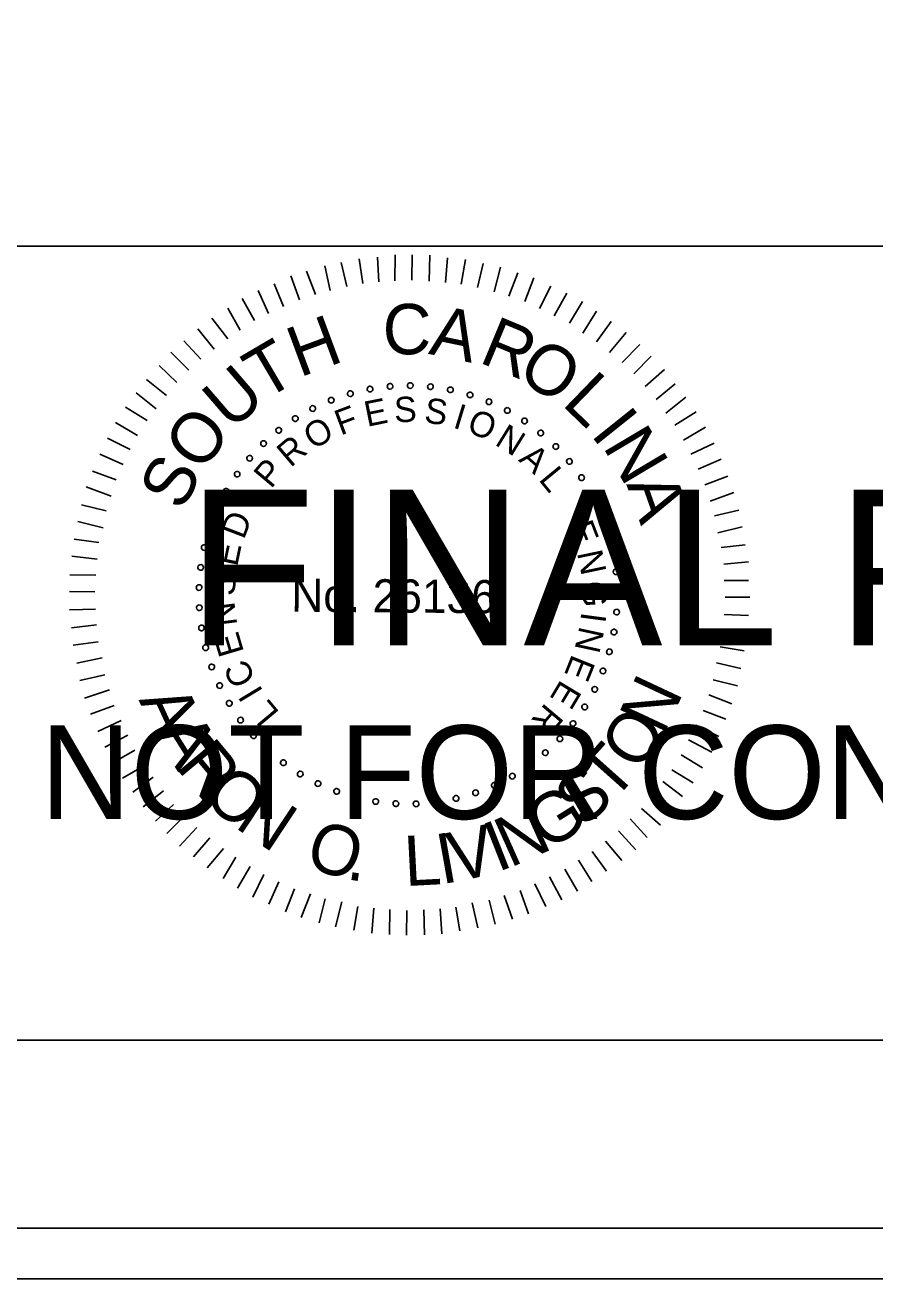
# Model space of a CAD drawing. Extents: x 967 to 1326, y 964 to 2864.
# Drawn here: x 1170.56 to 1189.3, y 1523.72 to 1551.36 of the extents above; entities that cross this region are included whole.
import ezdxf

# ---------------------------------------------------------------- set-up
doc = ezdxf.new("R2010")
doc.units = 0
for name, color, linetype in [('RD_PD_Final_TX', 7, 'Continuous'), ('RD_XS_TX_Elev_PR', 7, 'Continuous'), ('RD_XS_TX_Misc', 7, 'Continuous'), ('RD_XS_TX_ShdSlope', 7, 'Continuous')]:
    doc.layers.add(name, color=color, linetype=linetype)

msp = doc.modelspace()

# ---------------------------------------------------------------- linework, layer by layer
at = {"layer": 'RD_PD_Final_TX'}
for p, q in [((996.114, 1546.486), (1323.886, 1546.486)), ((1323.886, 1528.983), (996.114, 1528.983))]:
    msp.add_line(p, q, dxfattribs=at)
at = {"layer": 'RD_XS_TX_Elev_PR'}
for points in [[(967.409, 1523.72), (1326.285, 1523.72), (1326.285, 1743.72), (967.409, 1743.72)], [(988.525, 1524.84), (1326.285, 1524.84), (1326.285, 1742.6), (988.525, 1742.6)]]:
    msp.add_lwpolyline(points, close=True, dxfattribs=at)
at = {"layer": 'RD_XS_TX_ShdSlope'}
for p, q in [((1178.01, 1545.663), (1177.93, 1546.209)), ((1178.364, 1545.699), (1178.33, 1546.244)), ((1178.717, 1545.719), (1178.722, 1546.295)), ((1179.093, 1545.739), (1179.098, 1546.292)), ((1179.469, 1545.713), (1179.489, 1546.288)), ((1179.829, 1545.687), (1179.872, 1546.231)), ((1180.174, 1545.646), (1180.271, 1546.19)), ((1176.964, 1545.419), (1176.769, 1545.935)), ((1177.287, 1545.508), (1177.169, 1546.054)), ((1177.657, 1545.597), (1177.53, 1546.128)), ((1180.535, 1545.573), (1180.662, 1546.102)), ((1180.902, 1545.478), (1181.045, 1546.022)), ((1181.231, 1545.384), (1181.428, 1545.896)), ((1176.264, 1545.156), (1176.053, 1545.657)), ((1176.61, 1545.306), (1176.423, 1545.83)), ((1181.584, 1545.265), (1181.78, 1545.786)), ((1175.933, 1545.005), (1175.699, 1545.506)), ((1181.905, 1545.109), (1182.154, 1545.606)), ((1182.226, 1544.953), (1182.506, 1545.45)), ((1175.308, 1544.634), (1175.036, 1545.12)), ((1175.624, 1544.846), (1175.352, 1545.332)), ((1182.562, 1544.789), (1182.85, 1545.27)), ((1175.03, 1544.445), (1174.681, 1544.9)), ((1182.86, 1544.572), (1183.163, 1545.053)), ((1183.158, 1544.378), (1183.484, 1544.828)), ((1174.729, 1544.217), (1174.372, 1544.665)), ((1183.447, 1544.145), (1183.811, 1544.587)), ((1174.435, 1543.997), (1174.062, 1544.399)), ((1183.729, 1543.92), (1184.116, 1544.316)), ((1174.172, 1543.753), (1173.776, 1544.148)), ((1183.98, 1543.672), (1184.368, 1544.061)), ((1173.909, 1543.479), (1173.52, 1543.858)), ((1184.232, 1543.394), (1184.657, 1543.767)), ((1173.684, 1543.197), (1173.242, 1543.546)), ((1184.475, 1543.108), (1184.892, 1543.45)), ((1173.451, 1542.9), (1173.009, 1543.256)), ((1184.687, 1542.807), (1185.128, 1543.156)), ((1173.257, 1542.64), (1172.776, 1542.936)), ((1173.039, 1542.312), (1172.559, 1542.6)), ((1184.885, 1542.544), (1185.355, 1542.832)), ((1185.081, 1542.213), (1185.56, 1542.493)), ((1172.883, 1542.006), (1172.379, 1542.256)), ((1185.24, 1541.904), (1185.756, 1542.145)), ((1172.727, 1541.677), (1172.215, 1541.904)), ((1185.399, 1541.573), (1185.907, 1541.791)), ((1172.571, 1541.333), (1172.051, 1541.53)), ((1185.549, 1541.226), (1186.057, 1541.414)), ((1172.461, 1540.974), (1171.91, 1541.178)), ((1185.669, 1540.865), (1186.185, 1541.06)), ((1172.351, 1540.652), (1171.807, 1540.787)), ((1185.759, 1540.541), (1186.297, 1540.667)), ((1172.286, 1540.276), (1171.727, 1540.419)), ((1185.832, 1540.165), (1186.371, 1540.298)), ((1172.191, 1539.955), (1171.647, 1540.029)), ((1185.906, 1539.842), (1186.436, 1539.906)), ((1172.15, 1539.587), (1171.598, 1539.653)), ((1185.964, 1539.473), (1186.51, 1539.53)), ((1172.124, 1539.234), (1171.548, 1539.239)), ((1185.977, 1539.12), (1186.514, 1539.115)), ((1172.105, 1538.866), (1171.545, 1538.871)), ((1185.997, 1538.751), (1186.542, 1538.747)), ((1172.118, 1538.482), (1171.542, 1538.471)), ((1185.971, 1538.368), (1186.508, 1538.348)), ((1172.138, 1538.136), (1171.585, 1538.072)), ((1185.952, 1538.022), (1186.497, 1537.949)), ((1172.173, 1537.768), (1171.627, 1537.688)), ((1185.888, 1537.655), (1186.417, 1537.566)), ((1172.262, 1537.414), (1171.701, 1537.296)), ((1185.808, 1537.302), (1186.345, 1537.175)), ((1172.321, 1537.037), (1171.774, 1536.911)), ((1185.729, 1536.926), (1186.265, 1536.792)), ((1172.425, 1536.707), (1171.871, 1536.519)), ((1185.634, 1536.597), (1186.146, 1536.401)), ((1172.53, 1536.36), (1172.007, 1536.173)), ((1185.508, 1536.253), (1186.013, 1536.057)), ((1172.681, 1536.029), (1172.165, 1535.788)), ((1172.831, 1535.705), (1172.323, 1535.441)), ((1185.352, 1535.924), (1185.857, 1535.675)), ((1185.188, 1535.603), (1185.7, 1535.33)), ((1172.982, 1535.374), (1172.497, 1535.094)), ((1185.024, 1535.274), (1185.498, 1534.987)), ((1173.194, 1535.042), (1172.709, 1534.762)), ((1184.822, 1534.946), (1185.288, 1534.658)), ((1173.384, 1534.78), (1172.936, 1534.453)), ((1184.62, 1534.687), (1185.055, 1534.353)), ((1173.612, 1534.478), (1173.164, 1534.129)), ((1184.403, 1534.389), (1184.814, 1534.033)), ((1173.832, 1534.177), (1173.437, 1533.812)), ((1184.155, 1534.092), (1184.574, 1533.72)), ((1174.091, 1533.945), (1173.689, 1533.541)), ((1183.899, 1533.864), (1184.28, 1533.454)), ((1174.35, 1533.674), (1173.97, 1533.263)), ((1183.644, 1533.597), (1184.024, 1533.18)), ((1174.64, 1533.442), (1174.275, 1533.022)), ((1174.937, 1533.209), (1174.58, 1532.782)), ((1183.358, 1533.37), (1183.715, 1532.944)), ((1175.212, 1533.014), (1174.932, 1532.549)), ((1182.764, 1532.952), (1183.059, 1532.482)), ((1183.065, 1533.141), (1183.384, 1532.709)), ((1175.525, 1532.812), (1175.245, 1532.331)), ((1175.83, 1532.633), (1175.588, 1532.136)), ((1182.463, 1532.755), (1182.743, 1532.269)), ((1176.159, 1532.477), (1175.94, 1531.98)), ((1181.8, 1532.431), (1182.041, 1531.93)), ((1182.124, 1532.581), (1182.396, 1532.08)), ((1176.503, 1532.321), (1176.307, 1531.816)), ((1176.855, 1532.211), (1176.651, 1531.69)), ((1177.177, 1532.1), (1177.05, 1531.572)), ((1181.122, 1532.175), (1181.31, 1531.652)), ((1181.476, 1532.28), (1181.664, 1531.771)), ((1177.545, 1532.036), (1177.409, 1531.484)), ((1177.897, 1531.933), (1177.808, 1531.412)), ((1178.25, 1531.892), (1178.207, 1531.34)), ((1178.603, 1531.866), (1178.598, 1531.313)), ((1178.978, 1531.84), (1178.974, 1531.295)), ((1179.355, 1531.86), (1179.365, 1531.307)), ((1179.715, 1531.88), (1179.749, 1531.327)), ((1180.061, 1531.915), (1180.149, 1531.393)), ((1180.423, 1532.012), (1180.541, 1531.458)), ((1180.791, 1532.07), (1180.926, 1531.54))]:
    msp.add_line(p, q, dxfattribs=at)
for centre, start, end in [((1178.609, 1543.397), 5.0653, 185.0653), ((1179.055, 1543.414), 359.5268, 179.5268), ((1179.055, 1543.414), 179.5268, 359.5268), ((1179.5, 1543.388), 353.9884, 173.9884), ((1177.312, 1543.091), 21.6807, 201.6807), ((1177.734, 1543.235), 16.1422, 196.1422), ((1177.734, 1543.235), 196.1422, 16.1422), ((1178.168, 1543.337), 10.6038, 190.6038), ((1178.168, 1543.337), 190.6038, 10.6038), ((1178.609, 1543.397), 185.0653, 5.0653), ((1179.5, 1543.388), 173.9884, 353.9884), ((1179.94, 1543.319), 168.4499, 348.4499), ((1179.94, 1543.319), 348.4499, 168.4499), ((1180.372, 1543.208), 162.9114, 342.9114), ((1180.372, 1543.208), 342.9114, 162.9114), ((1176.906, 1542.908), 27.2191, 207.2191), ((1176.906, 1542.908), 207.2191, 27.2191), ((1177.312, 1543.091), 201.6807, 21.6807), ((1180.79, 1543.056), 157.373, 337.373), ((1180.79, 1543.056), 337.373, 157.373), ((1181.193, 1542.864), 151.8345, 331.8345), ((1181.193, 1542.864), 331.8345, 151.8345), ((1176.52, 1542.686), 32.7576, 212.7576), ((1176.52, 1542.686), 212.7576, 32.7576), ((1181.574, 1542.634), 146.2961, 326.2961), ((1181.574, 1542.634), 326.2961, 146.2961), ((1176.156, 1542.428), 38.2961, 218.2961), ((1176.156, 1542.428), 218.2961, 38.2961), ((1181.932, 1542.368), 140.7576, 320.7576), ((1181.932, 1542.368), 320.7576, 140.7576), ((1175.82, 1542.135), 43.8345, 223.8345), ((1175.82, 1542.135), 223.8345, 43.8345), ((1182.263, 1542.069), 135.2191, 315.2191), ((1182.263, 1542.069), 315.2191, 135.2191), ((1175.513, 1541.812), 49.373, 229.373), ((1175.513, 1541.812), 229.373, 49.373), ((1182.563, 1541.74), 129.6807, 309.6807), ((1182.563, 1541.74), 309.6807, 129.6807), ((1175.239, 1541.461), 54.9114, 234.9114), ((1175.239, 1541.461), 234.9114, 54.9114), ((1182.83, 1541.383), 124.1422, 304.1422), ((1182.83, 1541.383), 304.1422, 124.1422), ((1175, 1541.085), 60.4499, 240.4499), ((1175, 1541.085), 240.4499, 60.4499), ((1183.061, 1541.002), 118.6038, 298.6038), ((1183.061, 1541.002), 298.6038, 118.6038), ((1174.798, 1540.687), 65.9884, 245.9884), ((1174.798, 1540.687), 245.9884, 65.9884), ((1183.255, 1540.601), 113.0653, 293.0653), ((1183.255, 1540.601), 293.0653, 113.0653), ((1174.636, 1540.272), 71.5268, 251.5268), ((1174.636, 1540.272), 251.5268, 71.5268), ((1183.408, 1540.182), 107.5268, 287.5268), ((1183.408, 1540.182), 287.5268, 107.5268), ((1174.514, 1539.843), 77.0653, 257.0653), ((1174.514, 1539.843), 257.0653, 77.0653), ((1183.521, 1539.751), 101.9884, 281.9884), ((1183.521, 1539.751), 281.9884, 101.9884), ((1174.435, 1539.405), 82.6038, 262.6038), ((1174.435, 1539.405), 262.6038, 82.6038), ((1183.592, 1539.311), 96.4499, 276.4499), ((1183.592, 1539.311), 276.4499, 96.4499), ((1174.398, 1538.961), 88.1422, 268.1422), ((1174.398, 1538.961), 268.1422, 88.1422), ((1183.619, 1538.866), 90.9114, 270.9114), ((1183.619, 1538.866), 270.9114, 90.9114), ((1174.404, 1538.515), 93.6807, 273.6807), ((1174.404, 1538.515), 273.6807, 93.6807), ((1183.604, 1538.421), 85.373, 265.373), ((1183.604, 1538.421), 265.373, 85.373), ((1174.453, 1538.072), 99.2191, 279.2191), ((1174.453, 1538.072), 279.2191, 99.2191), ((1183.546, 1537.979), 79.8345, 259.8345), ((1183.546, 1537.979), 259.8345, 79.8345), ((1174.545, 1537.636), 104.7576, 284.7576), ((1174.545, 1537.636), 284.7576, 104.7576), ((1183.445, 1537.545), 74.2961, 254.2961), ((1183.445, 1537.545), 254.2961, 74.2961), ((1174.678, 1537.211), 110.2961, 290.2961), ((1174.678, 1537.211), 290.2961, 110.2961), ((1183.303, 1537.122), 68.7576, 248.7576), ((1183.303, 1537.122), 248.7576, 68.7576), ((1174.852, 1536.8), 115.8345, 295.8345), ((1174.852, 1536.8), 295.8345, 115.8345), ((1183.121, 1536.716), 63.2191, 243.2191), ((1183.121, 1536.716), 243.2191, 63.2191), ((1175.065, 1536.409), 121.373, 301.373), ((1175.065, 1536.409), 301.373, 121.373), ((1182.9, 1536.328), 57.6807, 237.6807), ((1182.9, 1536.328), 237.6807, 57.6807), ((1175.314, 1536.039), 126.9114, 306.9114), ((1175.314, 1536.039), 306.9114, 126.9114), ((1182.643, 1535.964), 52.1422, 232.1422), ((1182.643, 1535.964), 232.1422, 52.1422), ((1175.598, 1535.696), 132.4499, 312.4499), ((1175.598, 1535.696), 312.4499, 132.4499), ((1182.353, 1535.627), 46.6038, 226.6038), ((1182.353, 1535.627), 226.6038, 46.6038), ((1175.914, 1535.381), 137.9884, 317.9884), ((1175.914, 1535.381), 317.9884, 137.9884), ((1176.258, 1535.099), 143.5268, 323.5268), ((1176.258, 1535.099), 323.5268, 143.5268), ((1182.03, 1535.319), 41.0653, 221.0653), ((1182.03, 1535.319), 221.0653, 41.0653), ((1176.629, 1534.851), 149.0653, 329.0653), ((1176.629, 1534.851), 329.0653, 149.0653), ((1181.305, 1534.803), 29.9884, 209.9884), ((1181.68, 1535.043), 35.5268, 215.5268), ((1181.68, 1535.043), 215.5268, 35.5268), ((1177.021, 1534.639), 154.6038, 334.6038), ((1177.021, 1534.639), 334.6038, 154.6038), ((1180.908, 1534.6), 24.4499, 204.4499), ((1180.908, 1534.6), 204.4499, 24.4499), ((1181.305, 1534.803), 209.9884, 29.9884), ((1177.432, 1534.467), 160.1422, 340.1422), ((1177.432, 1534.467), 340.1422, 160.1422), ((1177.858, 1534.335), 165.6807, 345.6807), ((1177.858, 1534.335), 345.6807, 165.6807), ((1178.294, 1534.245), 351.2191, 171.2191), ((1179.627, 1534.232), 7.8345, 187.8345), ((1180.065, 1534.313), 13.373, 193.373), ((1180.065, 1534.313), 193.373, 13.373), ((1180.494, 1534.436), 18.9114, 198.9114), ((1180.494, 1534.436), 198.9114, 18.9114), ((1178.294, 1534.245), 171.2191, 351.2191), ((1178.737, 1534.198), 356.7576, 176.7576), ((1178.737, 1534.198), 176.7576, 356.7576), ((1179.183, 1534.193), 2.2961, 182.2961), ((1179.183, 1534.193), 182.2961, 2.2961), ((1179.627, 1534.232), 187.8345, 7.8345)]:
    msp.add_arc(centre, 0.0627, start, end, dxfattribs=at)

# ---------------------------------------------------------------- texts
at = {"layer": 'RD_XS_TX_Misc'}
for s, height, p in [('FINAL PLANS', 3.4375, (1174.145, 1537.685)), ('NOT FOR CONSTRUCTION', 2.0625, (1170.901, 1533.86))]:
    msp.add_text(s, height=height, dxfattribs=at).set_placement(p)
at = {"layer": 'RD_XS_TX_ShdSlope'}
for s, height, rotation, p in [('C', 1.11, 359.5482, (1178.442, 1544.108)), ('A', 1.11, 348.1981, (1179.439, 1544.115)), ('H', 1.11, 20.3637, (1176.614, 1543.587)), ('R', 1.11, 337.4344, (1180.541, 1543.937)), ('T', 1.11, 30.4992, (1175.828, 1543.072)), ('O', 1.108, 326.5869, (1181.366, 1543.609)), ('U', 1.11, 40.8022, (1175.102, 1542.403)), ('L', 1.11, 315.9488, (1182.373, 1543.003)), ('E', 0.557, 11.4103, (1178.103, 1542.503)), ('S', 0.557, 2.208, (1178.709, 1542.601)), ('S', 0.557, 352.6608, (1179.346, 1542.599)), ('F', 0.557, 20.6127, (1177.52, 1542.309)), ('I', 0.557, 343.1136, (1179.975, 1542.491)), ('O', 0.557, 338.4392, (1180.274, 1542.401)), ('I', 1.11, 308.6613, (1183.011, 1542.338)), ('O', 1.11, 52.0267, (1174.435, 1541.474)), ('O', 0.557, 30.8477, (1176.917, 1541.987)), ('N', 0.557, 328.2042, (1180.896, 1542.12)), ('N', 1.11, 300.7037, (1183.285, 1542.075)), ('R', 0.557, 40.3949, (1176.415, 1541.594)), ('A', 0.557, 318.657, (1181.424, 1541.762)), ('S', 1.108, 63.2511, (1174.029, 1540.619)), ('P', 0.557, 49.9421, (1175.985, 1541.124)), ('L', 0.557, 309.4546, (1181.869, 1541.339)), ('A', 1.11, 289.4792, (1183.814, 1541.243)), ('D', 0.557, 69.0364, (1175.386, 1540.003)), ('E', 0.557, 291.049, (1182.53, 1540.307)), ('E', 0.557, 78.2388, (1175.238, 1539.407)), ('N', 0.557, 281.8466, (1182.728, 1539.726)), ('S', 0.557, 87.786, (1175.187, 1538.772)), ('No. 26136', 0.7311, 359.5268, (1176.429, 1538.43)), ('G', 0.557, 272.2995, (1182.833, 1539.097)), ('N', 0.557, 97.3332, (1175.242, 1538.137)), ('I', 0.557, 262.4084, (1182.83, 1538.437)), ('E', 0.557, 106.5355, (1175.394, 1537.541)), ('N', 0.557, 257.7339, (1182.789, 1538.127)), ('C', 0.557, 116.4266, (1175.661, 1536.938)), ('E', 0.557, 248.1867, (1182.628, 1537.511)), ('I', 0.557, 121.1011, (1175.823, 1536.67)), ('E', 0.557, 238.9844, (1182.378, 1536.949)), ('N', 1.105, 64.8922, (1184.632, 1535.684)), ('A', 1.105, 294.7297, (1173.062, 1536.486)), ('L', 0.557, 129.9595, (1176.187, 1536.204)), ('R', 0.557, 229.782, (1182.041, 1536.435)), ('O', 1.105, 56.2059, (1184.102, 1534.874)), ('A', 1.105, 302.2892, (1173.414, 1535.72)), ('R', 1.105, 309.8487, (1173.865, 1535.007)), ('T', 1.105, 48.2685, (1183.515, 1534.211)), ('O', 1.105, 317.7861, (1174.434, 1534.33)), ('S', 1.105, 40.3311, (1182.842, 1533.636)), ('N', 1.105, 326.4725, (1175.158, 1533.686)), ('G', 1.105, 32.0198, (1182.059, 1533.14)), ('N', 1.105, 24.0824, (1181.252, 1532.776)), ('O', 1.105, 342.3472, (1176.697, 1532.82)), ('V', 1.105, 12.7741, (1180.033, 1532.457)), ('I', 1.105, 21.4605, (1180.976, 1532.681)), ('L', 1.105, 2.9677, (1178.943, 1532.379)), ('I', 1.105, 10.1523, (1179.743, 1532.418)), ('.', 1.105, 351.0336, (1177.623, 1532.536))]:
    msp.add_text(s, height=height, rotation=rotation, dxfattribs=at).set_placement(p)

doc.saveas('drawing.dxf')
